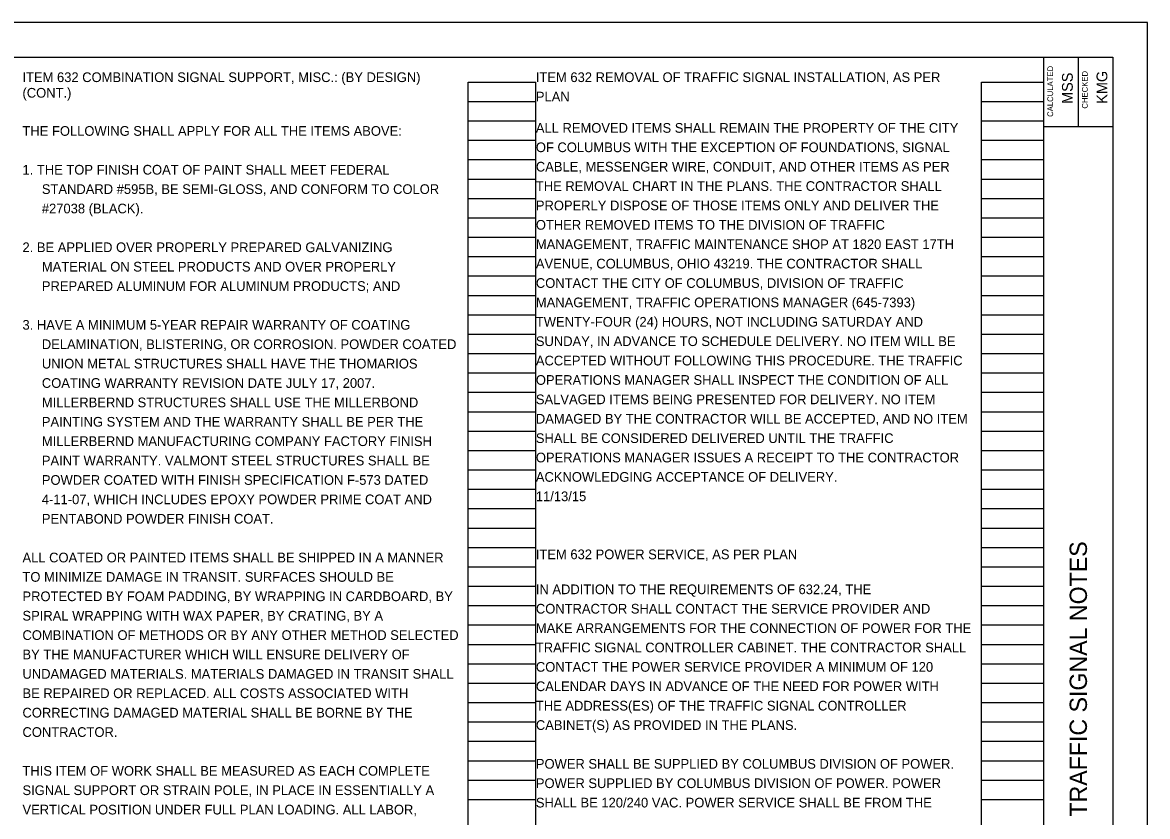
# Model space of a CAD drawing. Extents: x -27 to 74, y -37 to 38.
# Drawn here: x 17.23 to 33.49, y 3.03 to 14.49 of the extents above; entities that cross this region are included whole.
import ezdxf

# ---------------------------------------------------------------- set-up
doc = ezdxf.new("R2010")
doc.units = 0
for name, color, linetype in [('Level 63', 7, 'Continuous'), ('PF_P_Text', 7, 'Continuous'), ('SC_Scratch1', 7, 'Continuous'), ('SH_Cut_Line', 7, 'Continuous'), ('SH_Data', 7, 'Continuous'), ('SH_Text', 7, 'Continuous'), ('SN_P_Text', 7, 'Continuous')]:
    doc.layers.add(name, color=color, linetype=linetype)

msp = doc.modelspace()

# ---------------------------------------------------------------- linework, layer by layer
at = {"layer": 'PF_P_Text'}
for p, q in [((31.994, -7.008), (31.994, 13.992)), ((32.494, 13.992), (32.494, 12.992)), ((31.994, 12.992), (32.994, 12.992))]:
    msp.add_line(p, q, dxfattribs=at)
msp.add_lwpolyline([(1.494, 13.992), (32.994, 13.992), (32.994, -7.008), (1.494, -7.008)], close=True, dxfattribs=at)
at = {"layer": 'SC_Scratch1'}
for p, q in [((23.674, -6.528), (23.674, 13.632)), ((23.674, 13.632), (24.654, 13.632)), ((24.654, -6.528), (24.654, 13.632)), ((31.094, -6.528), (31.094, 13.632)), ((31.094, 13.632), (31.994, 13.632)), ((31.994, -6.528), (31.994, 13.632)), ((23.674, 13.352), (24.654, 13.352)), ((31.094, 13.352), (31.994, 13.352)), ((23.674, 13.072), (24.654, 13.072)), ((31.094, 13.072), (31.994, 13.072)), ((23.674, 12.792), (24.654, 12.792)), ((31.094, 12.792), (31.994, 12.792)), ((23.674, 12.512), (24.654, 12.512)), ((31.094, 12.512), (31.994, 12.512)), ((23.674, 12.232), (24.654, 12.232)), ((31.094, 12.232), (31.994, 12.232)), ((23.674, 11.952), (24.654, 11.952)), ((31.094, 11.952), (31.994, 11.952)), ((23.674, 11.672), (24.654, 11.672)), ((31.094, 11.672), (31.994, 11.672)), ((23.674, 11.392), (24.654, 11.392)), ((31.094, 11.392), (31.994, 11.392)), ((23.674, 11.112), (24.654, 11.112)), ((31.094, 11.112), (31.994, 11.112)), ((23.674, 10.832), (24.654, 10.832)), ((31.094, 10.832), (31.994, 10.832)), ((23.674, 10.552), (24.654, 10.552)), ((31.094, 10.552), (31.994, 10.552)), ((23.674, 10.272), (24.654, 10.272)), ((31.094, 10.272), (31.994, 10.272)), ((23.674, 9.992), (24.654, 9.992)), ((31.094, 9.992), (31.994, 9.992)), ((23.674, 9.712), (24.654, 9.712)), ((31.094, 9.712), (31.994, 9.712)), ((23.674, 9.432), (24.654, 9.432)), ((31.094, 9.432), (31.994, 9.432)), ((23.674, 9.152), (24.654, 9.152)), ((31.094, 9.152), (31.994, 9.152)), ((23.674, 8.872), (24.654, 8.872)), ((31.094, 8.872), (31.994, 8.872)), ((23.674, 8.592), (24.654, 8.592)), ((31.094, 8.592), (31.994, 8.592)), ((23.674, 8.312), (24.654, 8.312)), ((31.094, 8.312), (31.994, 8.312)), ((23.674, 8.032), (24.654, 8.032)), ((31.094, 8.032), (31.994, 8.032)), ((23.674, 7.752), (24.654, 7.752)), ((31.094, 7.752), (31.994, 7.752)), ((23.674, 7.472), (24.654, 7.472)), ((31.094, 7.472), (31.994, 7.472)), ((23.674, 7.192), (24.654, 7.192)), ((31.094, 7.192), (31.994, 7.192)), ((23.674, 6.912), (24.654, 6.912)), ((31.094, 6.912), (31.994, 6.912)), ((23.674, 6.632), (24.654, 6.632)), ((31.094, 6.632), (31.994, 6.632)), ((23.674, 6.352), (24.654, 6.352)), ((31.094, 6.352), (31.994, 6.352)), ((23.674, 6.072), (24.654, 6.072)), ((31.094, 6.072), (31.994, 6.072)), ((23.674, 5.792), (24.654, 5.792)), ((31.094, 5.792), (31.994, 5.792)), ((23.674, 5.512), (24.654, 5.512)), ((31.094, 5.512), (31.994, 5.512)), ((23.674, 5.232), (24.654, 5.232)), ((31.094, 5.232), (31.994, 5.232)), ((23.674, 4.952), (24.654, 4.952)), ((31.094, 4.952), (31.994, 4.952)), ((23.674, 4.672), (24.654, 4.672)), ((31.094, 4.672), (31.994, 4.672)), ((23.674, 4.392), (24.654, 4.392)), ((31.094, 4.392), (31.994, 4.392)), ((23.674, 4.112), (24.654, 4.112)), ((31.094, 4.112), (31.994, 4.112)), ((23.674, 3.832), (24.654, 3.832)), ((31.094, 3.832), (31.994, 3.832)), ((23.674, 3.552), (24.654, 3.552)), ((31.094, 3.552), (31.994, 3.552)), ((23.674, 3.272), (24.654, 3.272)), ((31.094, 3.272), (31.994, 3.272))]:
    msp.add_line(p, q, dxfattribs=at)
at = {"layer": 'SH_Cut_Line'}
msp.add_lwpolyline([(-0.506, -7.508), (33.494, -7.508), (33.494, 14.492), (-0.506, 14.492)], close=True, dxfattribs=at)

# ---------------------------------------------------------------- texts
at = {"layer": 'Level 63'}
for s, p in [('CALCULATED', (32.13, 13.129)), ('CHECKED', (32.63, 13.248))]:
    msp.add_text(s, height=0.0833, rotation=90, dxfattribs=at).set_placement(p)
at = {"layer": 'SH_Data'}
for s, p in [('ITEM 632 COMBINATION SIGNAL SUPPORT, MISC.: (BY DESIGN) ', (17.234, 13.632)), ('ITEM 632 REMOVAL OF TRAFFIC SIGNAL INSTALLATION, AS PER ', (24.654, 13.632)), ('(CONT.)', (17.234, 13.407)), ('PLAN', (24.654, 13.352)), ('ALL REMOVED ITEMS SHALL REMAIN THE PROPERTY OF THE CITY ', (24.654, 12.9)), ('OF COLUMBUS WITH THE EXCEPTION OF FOUNDATIONS, SIGNAL ', (24.654, 12.62)), ('CABLE, MESSENGER WIRE, CONDUIT, AND OTHER ITEMS AS PER ', (24.654, 12.34)), ('THE REMOVAL CHART IN THE PLANS. THE CONTRACTOR SHALL ', (24.654, 12.06)), ('PROPERLY DISPOSE OF THOSE ITEMS ONLY AND DELIVER THE ', (24.654, 11.78)), ('OTHER REMOVED ITEMS TO THE DIVISION OF TRAFFIC ', (24.654, 11.5)), ('MANAGEMENT, TRAFFIC MAINTENANCE SHOP AT 1820 EAST 17TH ', (24.654, 11.22)), ('AVENUE, COLUMBUS, OHIO 43219. THE CONTRACTOR SHALL ', (24.654, 10.94)), ('CONTACT THE CITY OF COLUMBUS, DIVISION OF TRAFFIC ', (24.654, 10.66)), ('MANAGEMENT, TRAFFIC OPERATIONS MANAGER (645-7393) ', (24.654, 10.38)), ('TWENTY-FOUR (24) HOURS, NOT INCLUDING SATURDAY AND ', (24.654, 10.1)), ('SUNDAY, IN ADVANCE TO SCHEDULE DELIVERY. NO ITEM WILL BE ', (24.654, 9.82)), ('ACCEPTED WITHOUT FOLLOWING THIS PROCEDURE. THE TRAFFIC ', (24.654, 9.54)), ('OPERATIONS MANAGER SHALL INSPECT THE CONDITION OF ALL ', (24.654, 9.26)), ('SALVAGED ITEMS BEING PRESENTED FOR DELIVERY. NO ITEM ', (24.654, 8.98)), ('DAMAGED BY THE CONTRACTOR WILL BE ACCEPTED, AND NO ITEM ', (24.654, 8.7)), ('SHALL BE CONSIDERED DELIVERED UNTIL THE TRAFFIC ', (24.654, 8.42)), ('OPERATIONS MANAGER ISSUES A RECEIPT TO THE CONTRACTOR ', (24.654, 8.14)), ('ACKNOWLEDGING ACCEPTANCE OF DELIVERY. ', (24.654, 7.86)), ('11/13/15', (24.654, 7.58)), ('ITEM 632 POWER SERVICE, AS PER PLAN', (24.654, 6.742)), ('IN ADDITION TO THE REQUIREMENTS OF 632.24, THE ', (24.654, 6.237)), ('CONTRACTOR SHALL CONTACT THE SERVICE PROVIDER AND ', (24.654, 5.957)), ('MAKE ARRANGEMENTS FOR THE CONNECTION OF POWER FOR THE ', (24.654, 5.677)), ('TRAFFIC SIGNAL CONTROLLER CABINET. THE CONTRACTOR SHALL ', (24.654, 5.397)), ('CONTACT THE POWER SERVICE PROVIDER A MINIMUM OF 120 ', (24.654, 5.117)), ('CALENDAR DAYS IN ADVANCE OF THE NEED FOR POWER WITH ', (24.654, 4.837)), ('THE ADDRESS(ES) OF THE TRAFFIC SIGNAL CONTROLLER ', (24.654, 4.557)), ('CABINET(S) AS PROVIDED IN THE PLANS.  ', (24.654, 4.277)), ('POWER SHALL BE SUPPLIED BY COLUMBUS DIVISION OF POWER. ', (24.654, 3.717)), ('POWER SUPPLIED BY COLUMBUS DIVISION OF POWER. POWER ', (24.654, 3.437)), ('SHALL BE 120/240 VAC. POWER SERVICE SHALL BE FROM THE ', (24.654, 3.157))]:
    msp.add_text(s, height=0.14, dxfattribs=at).set_placement(p)
at = {"layer": 'SH_Text'}
for s, height, p in [('MSS', 0.156, (32.414, 13.317)), ('KMG', 0.156, (32.914, 13.319)), ('TRAFFIC SIGNAL NOTES', 0.25, (32.619, 3.025))]:
    msp.add_text(s, height=height, rotation=90, dxfattribs=at).set_placement(p)
at = {"layer": 'SN_P_Text'}
for s, p in [('THE FOLLOWING SHALL APPLY FOR ALL THE ITEMS ABOVE:', (17.234, 12.856)), ('1. THE TOP FINISH COAT OF PAINT SHALL MEET FEDERAL ', (17.234, 12.296)), ('STANDARD #595B, BE SEMI-GLOSS, AND CONFORM TO COLOR ', (17.514, 12.016)), ('#27038 (BLACK).', (17.514, 11.736)), ('2. BE APPLIED OVER PROPERLY PREPARED GALVANIZING ', (17.234, 11.176)), ('MATERIAL ON STEEL PRODUCTS AND OVER PROPERLY ', (17.514, 10.896)), ('PREPARED ALUMINUM FOR ALUMINUM PRODUCTS; AND', (17.514, 10.616)), ('3. HAVE A MINIMUM 5-YEAR REPAIR WARRANTY OF COATING ', (17.234, 10.056)), ('DELAMINATION, BLISTERING, OR CORROSION. POWDER COATED ', (17.514, 9.776)), ('UNION METAL STRUCTURES SHALL HAVE THE THOMARIOS ', (17.514, 9.496)), ('COATING WARRANTY REVISION DATE JULY 17, 2007. ', (17.514, 9.216)), ('MILLERBERND STRUCTURES SHALL USE THE MILLERBOND ', (17.514, 8.936)), ('PAINTING SYSTEM AND THE WARRANTY SHALL BE PER THE ', (17.514, 8.656)), ('MILLERBERND MANUFACTURING COMPANY FACTORY FINISH ', (17.514, 8.376)), ('PAINT WARRANTY. VALMONT STEEL STRUCTURES SHALL BE ', (17.514, 8.096)), ('POWDER COATED WITH FINISH SPECIFICATION F-573 DATED ', (17.514, 7.816)), ('4-11-07, WHICH INCLUDES EPOXY POWDER PRIME COAT AND ', (17.514, 7.536)), ('PENTABOND POWDER FINISH COAT.', (17.514, 7.256)), ('ALL COATED OR PAINTED ITEMS SHALL BE SHIPPED IN A MANNER ', (17.234, 6.696)), ('TO MINIMIZE DAMAGE IN TRANSIT. SURFACES SHOULD BE ', (17.234, 6.416)), ('PROTECTED BY FOAM PADDING, BY WRAPPING IN CARDBOARD, BY ', (17.234, 6.136)), ('SPIRAL WRAPPING WITH WAX PAPER, BY CRATING, BY A ', (17.234, 5.856)), ('COMBINATION OF METHODS OR BY ANY OTHER METHOD SELECTED ', (17.234, 5.576)), ('BY THE MANUFACTURER WHICH WILL ENSURE DELIVERY OF ', (17.234, 5.296)), ('UNDAMAGED MATERIALS. MATERIALS DAMAGED IN TRANSIT SHALL ', (17.234, 5.016)), ('BE REPAIRED OR REPLACED. ALL COSTS ASSOCIATED WITH ', (17.234, 4.736)), ('CORRECTING DAMAGED MATERIAL SHALL BE BORNE BY THE ', (17.234, 4.456)), ('CONTRACTOR.', (17.234, 4.176)), ('THIS ITEM OF WORK SHALL BE MEASURED AS EACH COMPLETE ', (17.234, 3.616)), ('SIGNAL SUPPORT OR STRAIN POLE, IN PLACE IN ESSENTIALLY A ', (17.234, 3.336)), ('VERTICAL POSITION UNDER FULL PLAN LOADING. ALL LABOR, ', (17.234, 3.056))]:
    msp.add_text(s, height=0.14, rotation=0, dxfattribs=at).set_placement(p)

doc.saveas('drawing.dxf')
